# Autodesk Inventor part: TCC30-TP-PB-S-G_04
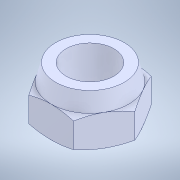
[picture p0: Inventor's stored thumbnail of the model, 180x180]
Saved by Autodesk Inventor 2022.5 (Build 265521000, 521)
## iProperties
Created: 2023-09
Part Number: TCC30-TP-PB-S-G_04
Material: 一般
Document SubType Name: Modeling
Designer: ImaoCorp
Density: 1 g/cm^3
Appearance: 既定
Author: ImaoCorp
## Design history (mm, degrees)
feature "TCC30-TP-PB-S-G_04"
node "ソリッド1"
